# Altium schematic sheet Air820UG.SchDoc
size 431 x 279 mm
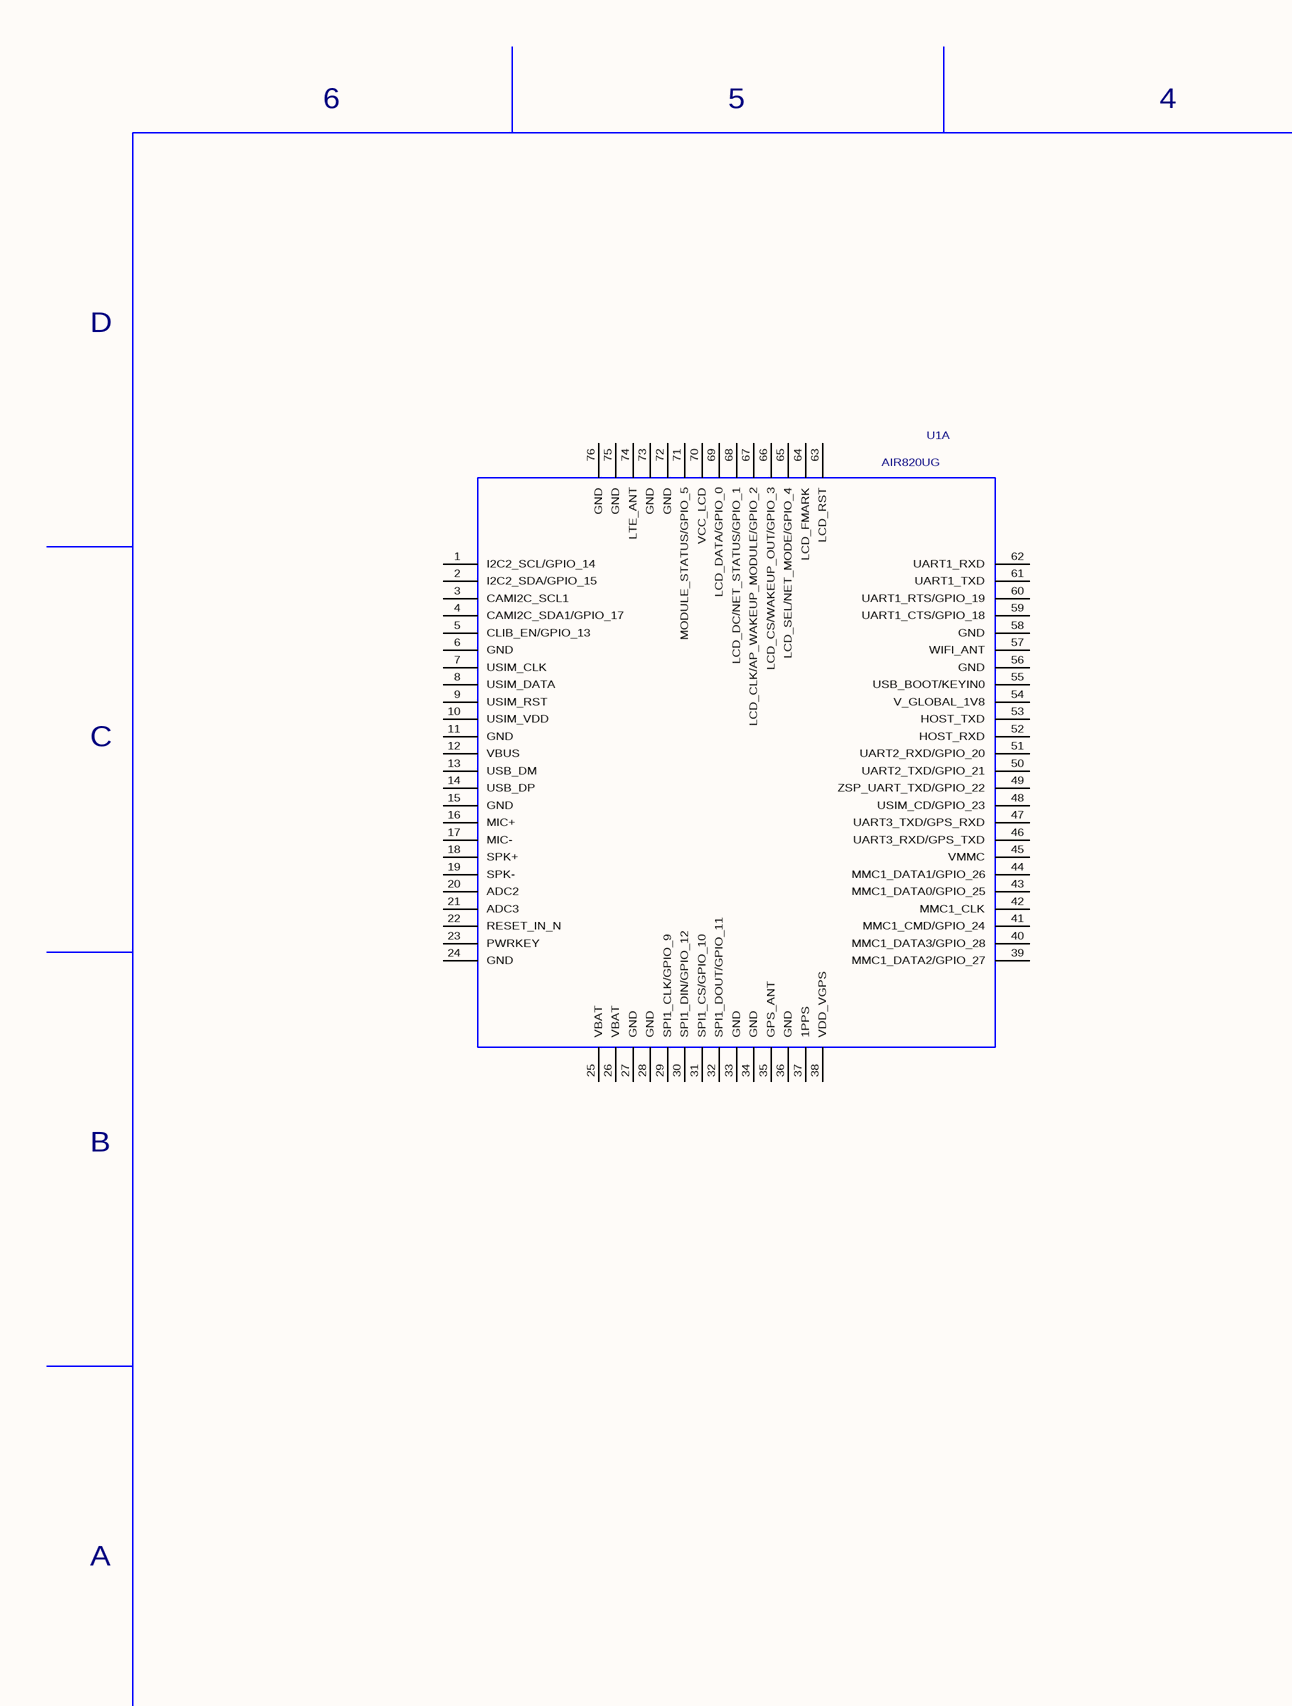
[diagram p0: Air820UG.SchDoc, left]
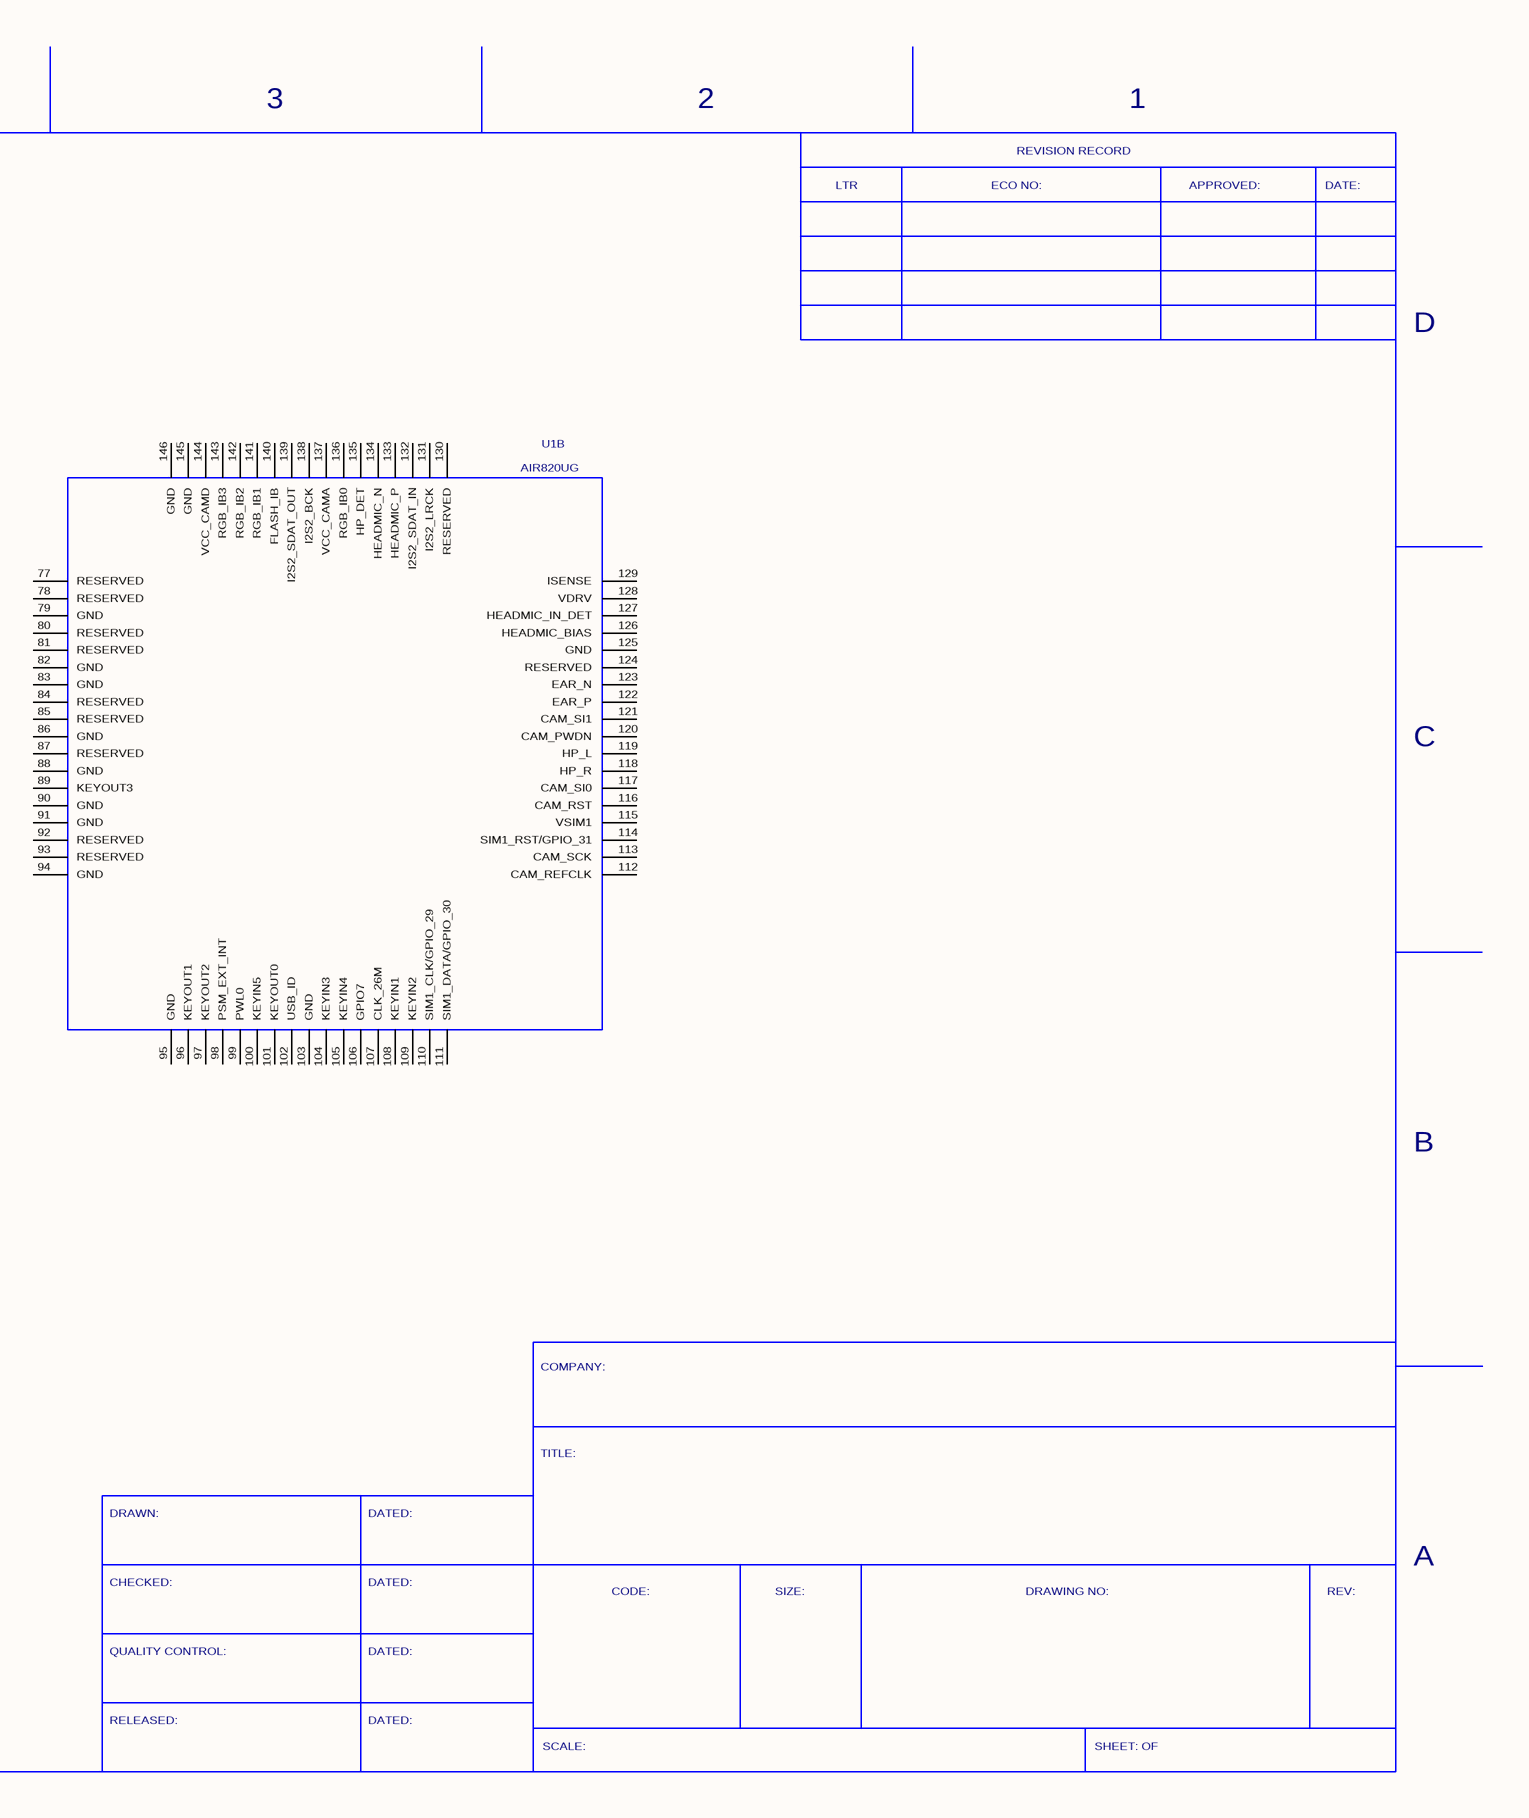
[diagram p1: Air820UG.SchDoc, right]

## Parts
U1  AIR820UG  [AIR820UG]  (parts A,B of 2)

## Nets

Not connected (* = marked no-connect by the designer): U1 1(I2C2_SCL/GPIO_14) 2(I2C2_SDA/GPIO_15) 3(CAMI2C_SCL1) 4(CAMI2C_SDA1/GPIO_17) 5(CLIB_EN/GPIO_13) 6(GND) 7(USIM_CLK) 8(USIM_DATA) 9(USIM_RST) 10(USIM_VDD) 11(GND) 12(VBUS) 13(USB_DM) 14(USB_DP) 15(GND) 16(MIC+) 17(MIC-) 18(SPK+) 19(SPK-) 20(ADC2) 21(ADC3) 22(RESET_IN_N) 23(PWRKEY) 24(GND) 25(VBAT) 26(VBAT) 27(GND) 28(GND) 29(SPI1_CLK/GPIO_9) 30(SPI1_DIN/GPIO_12) 31(SPI1_CS/GPIO_10) 32(SPI1_DOUT/GPIO_11) 33(GND) 34(GND) 35(GPS_ANT) 36(GND) 37(1PPS) 38(VDD_VGPS) 39(MMC1_DATA2/GPIO_27) 40(MMC1_DATA3/GPIO_28) 41(MMC1_CMD/GPIO_24) 42(MMC1_CLK) 43(MMC1_DATA0/GPIO_25) 44(MMC1_DATA1/GPIO_26) 45(VMMC) 46(UART3_RXD/GPS_TXD) 47(UART3_TXD/GPS_RXD) 48(USIM_CD/GPIO_23) 49(ZSP_UART_TXD/GPIO_22) 50(UART2_TXD/GPIO_21) 51(UART2_RXD/GPIO_20) 52(HOST_RXD) 53(HOST_TXD) 54(V_GLOBAL_1V8) 55(USB_BOOT/KEYIN0) 56(GND) 57(WIFI_ANT) 58(GND) 59(UART1_CTS/GPIO_18) 60(UART1_RTS/GPIO_19) 61(UART1_TXD) 62(UART1_RXD) 63(LCD_RST) 64(LCD_FMARK) 65(LCD_SEL/NET_MODE/GPIO_4) 66(LCD_CS/WAKEUP_OUT/GPIO_3) 67(LCD_CLK/AP_WAKEUP_MODULE/GPIO_2) 68(LCD_DC/NET_STATUS/GPIO_1) 69(LCD_DATA/GPIO_0) 70(VCC_LCD) 71(MODULE_STATUS/GPIO_5) 72(GND) 73(GND) 74(LTE_ANT) 75(GND) 76(GND) 77(RESERVED) 78(RESERVED) 79(GND) 80(RESERVED) 81(RESERVED) 82(GND) 83(GND) 84(RESERVED) 85(RESERVED) 86(GND) 87(RESERVED) 88(GND) 89(KEYOUT3) 90(GND) 91(GND) 92(RESERVED) 93(RESERVED) 94(GND) 95(GND) 96(KEYOUT1) 97(KEYOUT2) 98(PSM_EXT_INT) 99(PWL0) 100(KEYIN5) 101(KEYOUT0) 102(USB_ID) 103(GND) 104(KEYIN3) 105(KEYIN4) 106(GPIO7) 107(CLK_26M) 108(KEYIN1) 109(KEYIN2) 110(SIM1_CLK/GPIO_29) 111(SIM1_DATA/GPIO_30) 112(CAM_REFCLK) 113(CAM_SCK) 114(SIM1_RST/GPIO_31) 115(VSIM1) 116(CAM_RST) 117(CAM_SI0) 118(HP_R) 119(HP_L) 120(CAM_PWDN) 121(CAM_SI1) 122(EAR_P) 123(EAR_N) 124(RESERVED) 125(GND) 126(HEADMIC_BIAS) 127(HEADMIC_IN_DET) 128(VDRV) 129(ISENSE) 130(RESERVED) 131(I2S2_LRCK) 132(I2S2_SDAT_IN) 133(HEADMIC_P) 134(HEADMIC_N) 135(HP_DET) 136(RGB_IB0) 137(VCC_CAMA) 138(I2S2_BCK) 139(I2S2_SDAT_OUT) 140(FLASH_IB) 141(RGB_IB1) 142(RGB_IB2) 143(RGB_IB3) 144(VCC_CAMD) 145(GND) 146(GND)

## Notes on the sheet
- 6
- 5
- 4
- 3
- 2
- REVISION RECORD
- 1
- LTR
- ECO NO:
- APPROVED:
- DATE:
- D
- C
- B
- COMPANY:
- TITLE:
- DRAWN:
- DATED:
- A
- CHECKED:
- CODE:
- SIZE:
- DRAWING NO:
- REV:
- QUALITY CONTROL:
- RELEASED:
- SCALE:
- SHEET: OF

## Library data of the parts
U1 = AIR820UG: LTE Cat1 + GPS module;20.0*32.6*2.3mm; Manufacture: Luat; Geometry.Height: 2.3mm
